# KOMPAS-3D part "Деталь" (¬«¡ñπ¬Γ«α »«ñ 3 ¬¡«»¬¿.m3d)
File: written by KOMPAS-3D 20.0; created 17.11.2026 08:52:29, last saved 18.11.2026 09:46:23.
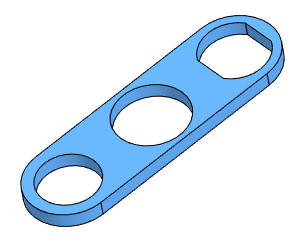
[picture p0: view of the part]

Document properties: Полное имя файла: D:\RicWork\Project-EPS32\box_compas\корпус\кондуктор под 3 кнопки.m3d

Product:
- Part/product: Деталь
    Масса: 0.00636192

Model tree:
1. Эскиз:1
2. Элемент выдавливания:1
     Расстояние 1 = 2.5
3. Эскиз:2  (with: Элемент выдавливания:1)
4. Элемент выдавливания:2
     Расстояние 2 = 2.5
